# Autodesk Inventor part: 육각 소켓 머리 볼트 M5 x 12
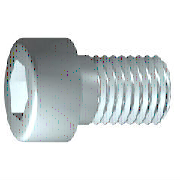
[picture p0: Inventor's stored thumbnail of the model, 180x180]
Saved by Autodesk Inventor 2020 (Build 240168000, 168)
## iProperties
Created: 2012-02
Part Number: 육각 소켓 머리 볼트 M5 x 12
Material: 강철, 연강
Description: 6각 소켓 머리 캡 나사
Document SubType Name: Modeling
Standard: ISO 4762
Designer: mdu-01
Standard Revision: Fourth edition 2004-03-01
Standards Organization: ISO
Language: ko-KR
Size Designation: M5 x 12
Categories: <MemberInstance><Categories><Category DisplayName="조임쇠" InternalName="e4da775c-781d-43d5-af7c-5136215cf5a6" Mnemonic="FSTN"><Category DisplayName="볼트" InternalN
Density: 7.75 g/cm^3
Appearance: 강철
Author: mdu-01
IsCustomPart: 1
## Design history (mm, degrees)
sketch "스케치1"
  geometry: L1 (-1.167, 0)-(12, 0); L2 (12, 0)-(12, 2.5); L3 (12, 2.5)-(2, 2.5); L4 (2, 2.5)-(1.509, 2.5); L5 (1.509, 2.5)-(0, 2.5); L6 (0, 2.5)-(0, 4.25); L7 (0, 4.25)-(-5, 4.25); L8 (-5, 4.25)-(-5, 2.309); L9 (-5, 2.309)-(-2.5, 2.309); L10 (-2.5, 2.309)-(-1.167, 0); L11 (-8.4, 0)-(15.4, 0) reference; L12 (0, -0.85)-(0, 5.1) reference; L13 (2, 2.5)-(0, 2.5)
  constraints: 22 end point, 6 parallel, 2 collinear, 2 perpendicular, 1 horizontal, 1 point on line
  dimensions: "d1" = 10 distance from line of L3.end L2 (= GEL); "d2" = 0.49086 distance of L4.end L3.end (computed from GAL); "d3" = 5 distance between parallel lines of L8 L6 (= KOH); "d4" = 2.5 distance of L8.end L9.end (= INTI); "d5" = 60 deg angle of L10 L1; "d6" = 5 diameter of L3 L1 (= GD); "d7" = 5 diameter of L5 L1 (= BDM); "d8" = 4.6188 diameter of L9 L1 (= 1.1547 x SW); "d9" = 8.5 diameter of L7 L1 (= KOD); "d26" = 12 distance between parallel lines of L12 L2 (= NLG)
revolve "본체" sketch "스케치1" stored, may be unused: angle "d10" = 90 deg
sketch "스케치2"
  geometry: L1 (0, -5.95)-(0, 5.95) reference; L2 (-5.95, 0)-(5.95, 0) reference; L3 (2.309, 0)-(1.155, -2); L4 (1.155, -2)-(-1.155, -2); L5 (-1.155, -2)-(-2.309, 0); L6 (-2.309, 0)-(-1.155, 2); L7 (-1.155, 2)-(1.155, 2); L8 (1.155, 2)-(2.309, 0); 2 further points
  constraints: 12 end point, 1 coincident, 1 horizontal alignment, 1 point on line, 12 other
extrude "슬롯" join sketch "스케치2" stored distance "d11" = 10; taper "d12" = 0 deg
workplane "Work Plane1"
fillet "Fillet2" dims "d30" = 0.1 (= R)
body "Solid1"
fillet "모깎기1" dims "d17" = 0.5 (= RR)
feature "스레드" dims "d13" = 10 (= GEL), "d14" = 0
chamfer "모따기1" distance "d15" = 0.49076 (= -0.5 x SPD + 0.5 x GD); stored, may be unused: second distance "d16" = 0.49076 (= GUL), angle "d27" = 45 deg
other parameters: "GD" = 5 [user parameter; used in 2 equation terms], "NLG" = 12 [user parameter; used in 1 equation term], "GEL" = 10 [user parameter; used in 2 equation terms], "KOD" = 8.5 [user parameter; used in 1 equation term], "KOH" = 5 [user parameter; used in 1 equation term], "INTI" = 2.5 [user parameter; used in 1 equation term], "GAL" = 0.49076 (= 0.61345 x PTC) [user parameter; used in 1 equation term], "GUL" = 0.49076 (= 0.61345 x PTC) [user parameter; used in 1 equation term], "BDM" = 5 (= NND) [user parameter; used in 1 equation term], "SW" = 4 [user parameter; used in 2 equation terms], "RR" = 0.5 [user parameter; used in 1 equation term], "SPD" = 4.01848 (= NND - 1.2269 x PTC) [user parameter; used in 1 equation term], "d19" = 0, "d28" = 0, "d29" = 0, "R" = 0.1 [user parameter; used in 1 equation term], "TOA" = 30 deg [user parameter], "GD1" = 4.01848 (= THREADDIA - 1.2269 x PTC) [user parameter], "THREADDIA" = 5 [user parameter; used in 1 equation term], "FAWI" = 45 deg [user parameter], "TPU" = 12.5 (computed from PTC) [user parameter], "PTC" = 0.8 [user parameter; used in 5 equation terms], "NND" = 5 [user parameter; used in 2 equation terms], "E0" = 4.62 (= 1.155 x SW) [user parameter]
